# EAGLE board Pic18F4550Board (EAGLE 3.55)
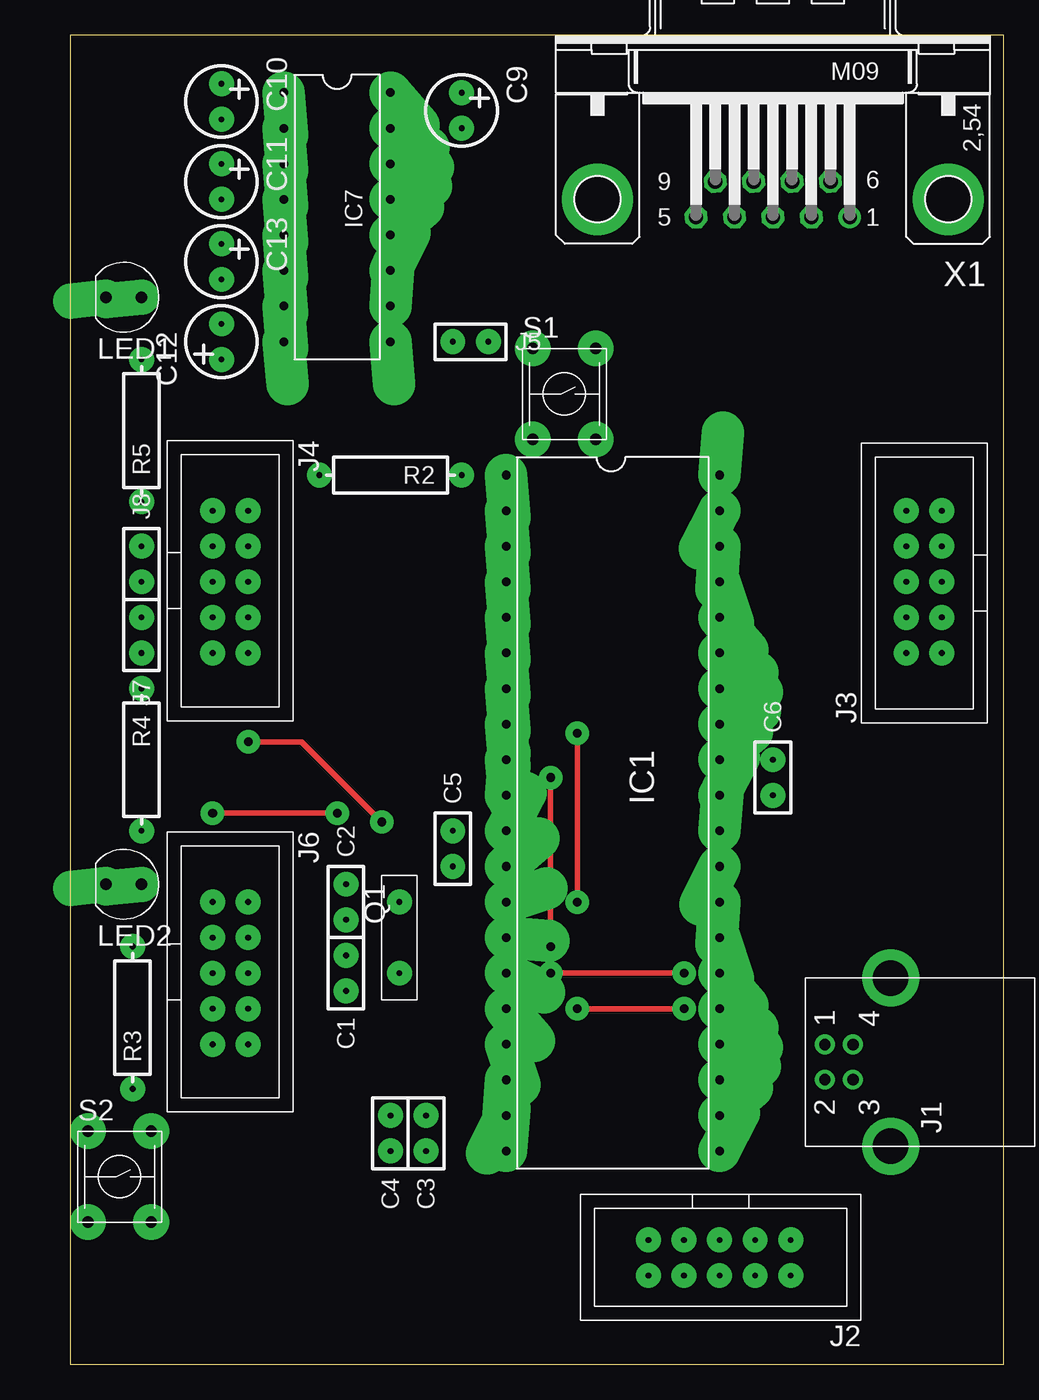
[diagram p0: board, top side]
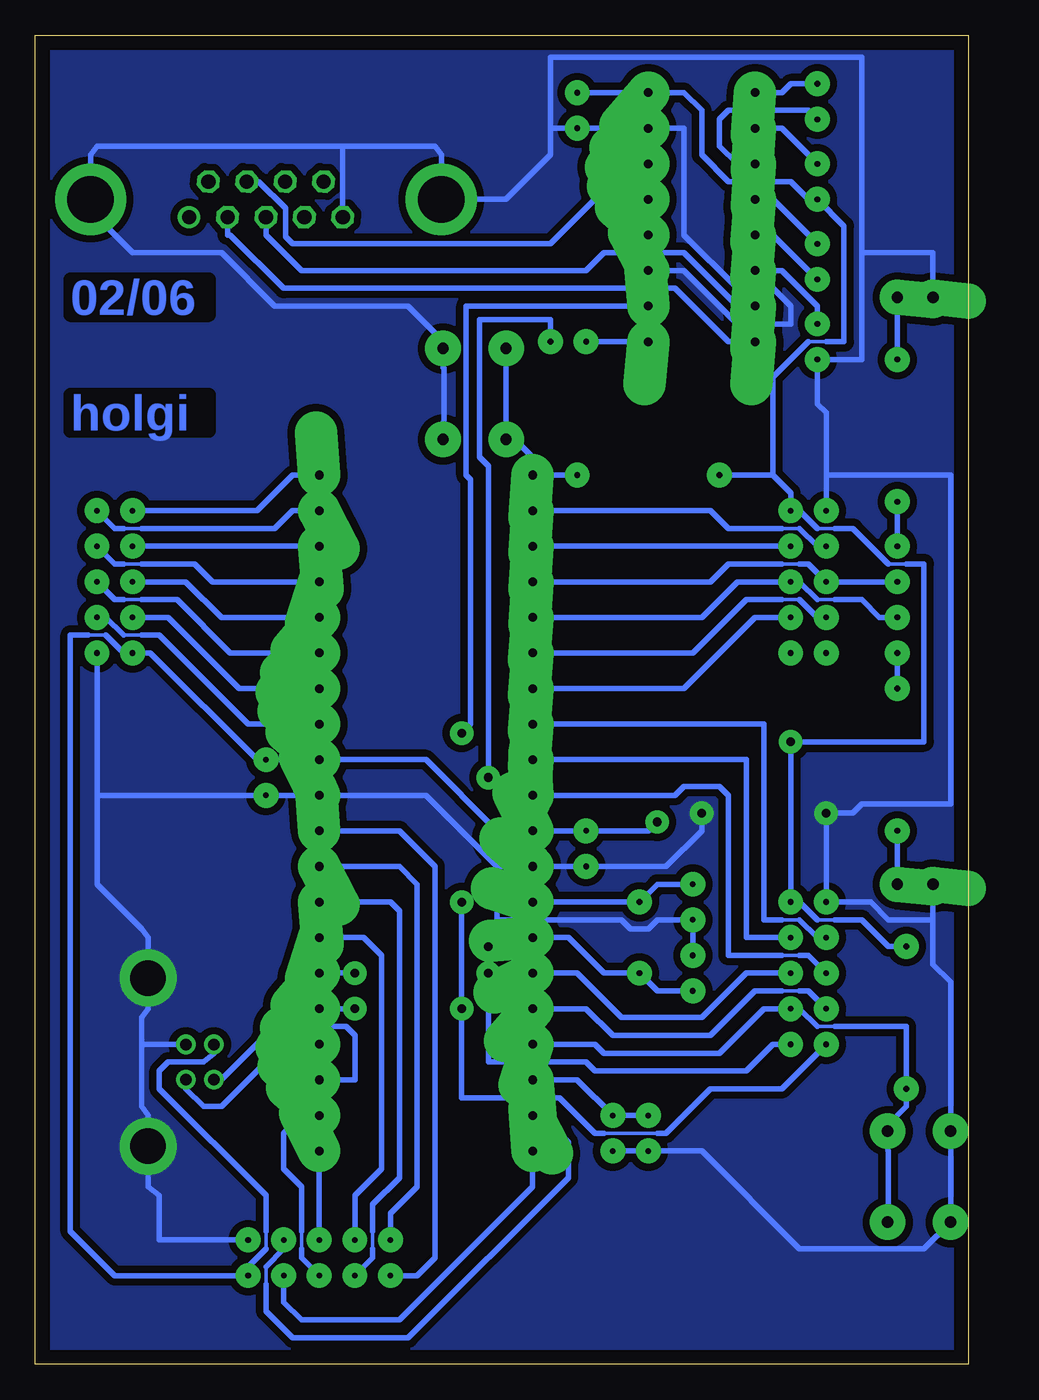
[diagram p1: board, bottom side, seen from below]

Size 66.66 x 94.92 mm. Coordinates in mm from the lower left corner, seen from the top.
Outline: 0,0 66.66,0 66.66,94.92 0,94.92 0,0
Copper layers used: Top, Bottom

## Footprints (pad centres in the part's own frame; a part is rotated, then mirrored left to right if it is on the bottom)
RM2,5 = drill 0.406 pad 1.778 round:  -1.27,0;  1.27,0
KO01 = drill 0.406 pad 1.778 round:  -1.27,0;  1.27,0
L-40B = drill 0.61 pad 3.048 offset:  -24.13,-7.62;  -21.59,-7.62;  -8.89,-7.62;  -6.35,-7.62;  -19.05,-7.62;  -16.51,-7.62;  -11.43,-7.62;  -13.97,-7.62;  -3.81,-7.62;  -1.27,-7.62;  1.27,-7.62;  3.81,-7.62;  6.35,-7.62;  8.89,-7.62;  11.43,-7.62;  13.97,-7.62;  16.51,-7.62;  19.05,-7.62;  21.59,-7.62;  24.13,-7.62;  24.13,7.62;  21.59,7.62;  19.05,7.62;  16.51,7.62;  13.97,7.62;  11.43,7.62;  8.89,7.62;  6.35,7.62;  3.81,7.62;  1.27,7.62;  -1.27,7.62;  -3.81,7.62;  -6.35,7.62;  -8.89,7.62;  -11.43,7.62;  -13.97,7.62;  -16.51,7.62;  -19.05,7.62;  -21.59,7.62;  -24.13,7.62
L-16B = drill 0.61 pad 3.048 offset:  -8.89,-3.81;  -6.35,-3.81;  6.35,-3.81;  8.89,-3.81;  -3.81,-3.81;  -1.27,-3.81;  3.81,-3.81;  1.27,-3.81;  8.89,3.81;  6.35,3.81;  3.81,3.81;  1.27,3.81;  -1.27,3.81;  -3.81,3.81;  -6.35,3.81;  -8.89,3.81
B_B = drill 2.54 pad 4.064 round: 1 6,-2.7; 2 -6,-2.7 | drill 0.813 pad 1.422 round:  1.25,0;  -1.25,0;  1.25,2;  -1.25,2
5 = drill 0.406 pad 1.778 round:  0,0;  2.54,0;  5.08,0;  7.62,0;  10.16,0;  10.16,2.54;  7.62,2.54;  5.08,2.54;  2.54,2.54;  0,2.54
MPER = drill 0.406 pad 1.778 round:  -1.27,0;  1.27,0
D_5MM = drill 0.813 pad 2.54 offset:  -1.27,0;  1.27,0
ARZ_ST = drill 0.406 pad 1.778 round:  -2.54,0;  2.54,0
S04 = drill 0.406 pad 1.778 round:  -5.08,0;  5.08,0
US = drill 0.813 pad 2.54 round:  0,0;  4.5,0;  4.5,6.5;  0,6.5
9HP = drill 1.016 pad 1.6 octagon:  5.486,1.27;  2.743,1.27;  0,1.27;  -2.743,1.27;  4.115,-1.27;  1.372,-1.27;  -1.372,-1.27;  -4.115,-1.27 | drill 1.016 pad 1.6 round:  -5.486,1.27 | drill 3.302 pad 5.08 round:  -12.522,0;  12.522,0

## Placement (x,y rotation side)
C1  15p  [RM2,5]  19.68,27.94 270 top
C2  15p  [RM2,5]  19.68,33.02 90 top
C3  100n  [RM2,5]  25.4,16.51 270 top
C4  100n  [RM2,5]  22.86,16.51 270 top
C5  100n  [RM2,5]  27.3,36.83 90 top
C6  100n  [RM2,5]  50.16,41.91 90 top
C9  10u  [KO01]  27.94,89.53 270 top
C10  1u  [KO01]  10.79,90.17 270 top
C11  1u  [KO01]  10.79,84.45 270 top
C12  1u  [KO01]  10.79,73.03 90 top
C13  1u  [KO01]  10.79,78.74 270 top
IC1  P18F4550  [L-40B]  38.73,39.37 270 top
IC7  MAX232  [L-16B]  19.05,81.92 270 top
J1  USB_B  [B_B]  55.88,21.59 90 top
J2  8BITPORT  [5]  51.44,8.89 180 top
J3  8BITPORT  [5]  62.23,50.8 90 top
J4  8BITPORT  [5]  10.16,60.96 270 top
J5  JUMPER  [MPER]  28.57,73.03 0 top
J6  8BITPORT  [5]  10.16,33.02 270 top
J7  JUMPER  [MPER]  5.08,52.07 270 top
J8  JUMPER  [MPER]  5.08,57.15 90 top
LED1  Green  [D_5MM]  3.81,76.2 180 top
LED2  Red  [D_5MM]  3.81,34.29 180 top
Q1  20.0MHz  [ARZ_ST]  23.5,30.48 270 top
R2  10k  [S04]  22.86,63.5 180 top
R3  10k  [S04]  4.45,24.77 90 top
R4  1k  [S04]  5.08,43.18 270 top
R5  1k  [S04]  5.08,66.67 90 top
S1  Reset  [US]  33.02,66.04 0 top
S2  Boot  [US]  1.27,10.16 0 top
X1  M09HP  [9HP]  50.16,83.19 180 top

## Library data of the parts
C1-C6 IC1 J2-J8 Q1 R2-R5 S1 S2 = holg_plt
C9-C13 LED1 LED2 = holgnorm
IC7 = maxim
J1 = 8031bord
X1 = subd-a

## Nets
+5V: C5. C6. C9. C11. IC1. IC7. J1. J2. J3. J4. J6. R2. R3.
GND: C1. C2. C3. C4. C5. C6. C9. C12. IC1. IC7. J1. J1.1 J1.2 J2. J3. J4. J6. LED1. LED2. S1. S2. X1.
N$1: C3. C4. IC1.
N$2: C12. IC7.
N$3: IC1. J2.
N$4: C2. IC1. Q1.
N$5: C1. IC1. Q1.
N$6: IC1. J2.
N$7: IC1. J2.
N$8: IC1. J1.
N$9: IC1. J1.
N$10: IC1. J2.
N$11: IC1. J2.
N$12: IC1. J2.
N$13: IC1. J2.
N$14: IC1. J2.
N$15: IC1. J3.
N$16: IC1. R2. S1.
N$17: IC1. J3.
N$18: IC1. J3.
N$19: IC1. J3.
N$20: IC1. J3.
N$21: IC1. J3.
N$22: IC1. J3.
N$23: IC1. J3.
N$24: C11. IC7.
N$25: C10. IC7.
N$26: C13. IC7.
N$27: C10. IC7.
N$28: C13. IC7.
N$29: IC1. J4.
N$30: IC1. J4.
N$31: IC1. J4. J8.
N$32: IC1. J4. J7.
N$33: IC1. J4.
N$34: IC1. J4.
N$35: IC7. J5.
N$40: LED2. R4.
N$41: LED1. R5.
N$42: J8. R5.
N$43: J7. R4.
RC0: IC1. J6.
RC1: IC1. J6.
RC2: IC1. J6. R3. S2.
RE0: IC1. J6.
RE1: IC1. J6.
RE2: IC1. J6.
RTS_OUT: IC7. X1.
RXD: IC1. J5. J6.
RXD_IN: IC7. X1.
TXD: IC1. IC7. J6.
TXD_OUT: IC7. X1.

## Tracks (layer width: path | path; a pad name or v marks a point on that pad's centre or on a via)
+5V  (via drill 0.61 pad 1.68)
  Top 0.406: v12.7,44.45 16.51,44.45 v22.23,38.73
  Bottom 0.254: 9.53,59.69 10.79,59.69 | 50.16,8.26 50.16,9.53 | 11.43,73.03 10.16,73.03 | 9.53,31.75 10.79,31.75 | 4.45,57.15 5.71,57.15 | 62.87,52.07 61.59,52.07
  Bottom 0.406: 13.97,63.5 12.7,62.23 J4. 12.06,60.96 10.79,59.69 | 13.97,63.5 R2. | 9.53,59.69 8.26,59.69 5.71,57.15 | v22.23,38.73 22.86,38.1 C5. 31.11,38.1 33.66,38.1 38.73,43.18 46.35,43.18 C6. 50.8,43.18 58.42,50.8 J3. 60.33,50.8 61.59,52.07 | 50.16,8.26 51.44,6.99 J2. 60.96,6.35 64.14,9.53 64.14,52.07 62.87,52.07 | 50.16,9.53 50.16,12.06 57.78,19.68 57.78,20.95 57.15,21.59 54.61,21.59 53.88,22.23 53.88,22.84 | 27.94,90.81 IC7. 20.32,90.81 19.05,89.53 19.05,86.36 17.14,84.45 12.7,84.45 11.43,83.19 C11. 8.89,81.28 8.89,73.03 10.16,73.03 | 13.97,63.5 13.97,70.48 11.43,73.03 | 10.79,31.75 12.06,33.02 J6. v12.7,44.45 3.17,44.45 3.17,57.15 4.45,57.15 | 9.53,31.75 7.62,31.75 5.71,29.84 R3.
GND  (via drill 0.61 pad 1.68)
  Top 0.406: v10.16,39.37 v19.05,39.37
  Bottom 0.406: C3. C4. 19.05,15.24 12.06,8.26 3.17,8.26 1.27,10.16 S2. 1.27,27.3 2.54,28.57 2.54,31.75 | 19.68,29.21 19.68,31.75 22.23,31.75 22.86,31.11 24.13,31.11 24.77,31.75 33.66,31.75 33.66,35.56 | 33.66,35.56 31.11,35.56 27.3,35.56 21.59,35.56 19.05,38.1 v19.05,39.37 | 33.66,35.56 38.73,40.64 46.35,40.64 50.16,40.64 62.23,40.64 | 62.23,40.64 62.23,50.8 | 51.44,8.89 57.78,8.89 57.78,12.06 58.58,12.7 J1.2 58.58,17.78 59.05,18.41 59.05,22.86 | 55.88,22.84 57.78,22.84 57.78,22.86 59.05,22.86 | 59.05,22.86 59.05,24.77 58.58,25.4 J1.1 58.58,30.48 59.05,31.11 62.23,34.29 62.23,40.64 | 10.16,63.5 10.16,67.94 10.79,68.58 10.79,71.75 7.62,71.75 7.62,79.38 | 7.62,79.38 7.62,93.34 29.84,93.34 29.84,88.27 | 29.84,88.27 C9. 22.86,88.27 20.32,88.27 20.32,80.64 16.51,76.83 13.97,76.83 12.7,75.56 12.7,74.3 16.51,74.3 20.32,78.11 22.86,78.11 | 29.84,88.27 29.84,86.36 33.02,83.19 X1. 37.64,86.36 38.1,87 44.45,87 | 44.68,81.92 44.68,87 44.45,87 | 44.45,87 62.23,87 62.69,86.36 62.69,83.19 62.69,82.37 59.69,79.38 53.34,79.38 49.53,75.56 40.01,75.56 37.52,73.08 37.52,72.54 37.52,71.17 37.47,71.12 37.47,67.31 37.52,67.25 37.52,66.04 | 2.54,31.75 LED2. | 2.54,31.75 5.71,31.75 6.99,33.02 10.16,33.02 v10.16,39.37 8.26,39.37 7.62,40.01 1.27,40.01 1.27,63.5 10.16,63.5 | LED1. 2.54,79.38 7.62,79.38 | 10.16,63.5 10.16,60.96
  pour Bottom (isolate 0.508): 0.64,0.64 0.64,93.98 66.04,93.98 66.04,0.64
N$1
  Bottom 0.406: 22.86,17.78 25.4,17.78 27.94,20.32 31.11,20.32
N$2
  Bottom 0.406: C12. 10.79,75.56 13.34,78.11 15.24,78.11
N$3
  Bottom 0.406: 46.35,38.1 40.64,38.1 38.1,35.56 38.1,7.62 39.37,6.35 41.27,6.35
N$4
  Bottom 0.406: 31.11,33.02 23.5,33.02 22.23,34.29 C2.
N$5
  Bottom 0.406: 31.11,30.48 28.57,30.48 26.04,27.94 Q1. 22.23,26.67 C1.
N$6
  Bottom 0.406: 46.35,35.56 40.64,35.56 39.37,34.29 39.37,12.7 41.27,10.79 41.27,8.89
N$7
  Bottom 0.254: 42.55,8.26 42.55,9.53
  Bottom 0.406: 46.35,33.02 41.27,33.02 40.64,32.38 40.64,13.34 42.55,11.43 42.55,9.53 | 43.81,6.35 42.55,7.62 42.55,8.26
N$8
  Bottom 0.406: 46.35,20.32 43.81,20.32 43.81,23.5 44.45,24.13 49.53,24.13 52.07,21.59 53.34,20.34 J1.
N$9
  Bottom 0.406: 55.88,20.34 55.88,19.68 54.61,18.41 53.34,18.41 48.9,22.86 46.35,22.86
N$10
  Bottom 0.406: 46.35,30.48 43.18,30.48 41.91,29.21 41.91,13.97 43.81,12.06 43.81,8.89
N$11
  Bottom 0.254: 47.62,8.26 47.62,9.53
  Bottom 0.406: 46.35,17.78 47.62,17.78 48.9,16.51 48.9,13.97 47.62,12.7 47.62,9.53 | 46.35,6.35 47.62,7.62 47.62,8.26
N$12
  Bottom 0.406: 46.35,8.89 46.35,15.24
N$13
  Bottom 0.406: 31.11,15.24 31.11,12.7 40.64,3.17 47.62,3.17 48.9,4.45 48.9,6.35
N$14
  Bottom 0.254: 50.16,5.71 50.16,6.99
  Bottom 0.406: 31.11,17.78 30.48,17.78 28.57,15.88 28.57,13.34 40.01,1.91 48.26,1.91 50.16,3.81 50.16,5.71 | 48.9,8.89 48.9,8.26 50.16,6.99
N$15
  Bottom 0.406: IC1. 48.26,63.5 50.8,60.96 59.69,60.96
N$16
  Bottom 0.406: 27.94,63.5 31.11,63.5 31.11,64.77 32.38,66.04 33.02,66.04 S1.
N$17
  Bottom 0.254: 59.05,59.69 60.33,59.69
  Bottom 0.406: 46.35,60.96 48.26,60.96 49.53,59.69 59.05,59.69 | 62.23,60.96 60.96,59.69 60.33,59.69
N$18
  Bottom 0.406: 46.35,58.42 59.69,58.42
N$19
  Bottom 0.254: 59.05,57.15 60.33,57.15
  Bottom 0.406: 46.35,55.88 53.98,55.88 55.24,57.15 59.05,57.15 | 62.23,58.42 60.96,57.15 60.33,57.15
N$20
  Bottom 0.406: 46.35,53.34 53.34,53.34 55.88,55.88 59.69,55.88
N$21
  Bottom 0.254: 59.05,54.61 60.33,54.61
  Bottom 0.406: 46.35,50.8 52.7,50.8 56.52,54.61 59.05,54.61 | 62.23,55.88 60.96,54.61 60.33,54.61
N$22
  Bottom 0.406: 46.35,48.26 52.07,48.26 57.15,53.34 59.69,53.34
N$23
  Bottom 0.254: 59.05,52.07 60.33,52.07
  Bottom 0.406: 46.35,45.72 51.44,45.72 57.78,52.07 59.05,52.07 | 62.23,53.34 61.59,53.34 60.33,52.07
N$24
  Bottom 0.406: 15.24,88.27 13.34,88.27 10.79,85.72
N$25
  Bottom 0.406: 15.24,85.72 16.51,85.72 17.78,87 17.78,88.9 17.14,89.53 11.43,89.53 C10.
N$26
  Bottom 0.406: 15.24,80.64 13.97,80.64 C13.
N$27
  Bottom 0.406: 15.24,90.81 13.34,90.81 12.7,91.44 10.79,91.44
N$28
  Bottom 0.406: 15.24,83.19 13.97,83.19 10.79,80.01
N$29
  Bottom 0.254: 12.06,59.69 13.34,59.69
  Bottom 0.406: 31.11,60.96 18.41,60.96 17.14,59.69 13.34,59.69 | 10.16,58.42 10.79,58.42 12.06,59.69
N$30
  Bottom 0.406: 12.7,58.42 31.11,58.42
N$31
  Bottom 0.254: 12.06,57.15 13.34,57.15
  Bottom 0.406: 12.06,57.15 11.43,57.15 10.16,55.88 5.08,55.88 | 31.11,55.88 18.41,55.88 17.14,57.15 13.34,57.15
N$32
  Bottom 0.254: 9.53,54.61 10.79,54.61
  Bottom 0.406: 31.11,53.34 19.05,53.34 16.51,55.88 12.7,55.88 12.06,55.88 10.79,54.61 | 5.08,53.34 6.35,53.34 7.62,54.61 9.53,54.61
N$33
  Bottom 0.254: 12.06,54.61 13.34,54.61
  Bottom 0.406: 31.11,50.8 19.68,50.8 15.88,54.61 13.34,54.61 | 10.16,53.34 10.79,53.34 12.06,54.61
N$34
  Bottom 0.406: 31.11,48.26 20.32,48.26 15.24,53.34 12.7,53.34
N$35
  Bottom 0.406: 22.86,73.03 27.3,73.03
N$40
  Bottom 0.406: 5.08,34.29 R4.
N$41
  Bottom 0.406: R5. 5.08,76.2
N$42
  Bottom 0.406: J8. 5.08,61.59
N$43
  Bottom 0.406: 5.08,48.26 J7.
RC0
  Bottom 0.406: 12.7,27.94 15.88,27.94 19.05,24.77 24.77,24.77 27.94,27.94 31.11,27.94
RC1
  Bottom 0.254: 12.06,26.67 13.34,26.67
  Bottom 0.406: 31.11,25.4 27.3,25.4 25.4,23.5 18.41,23.5 15.24,26.67 13.34,26.67 | 10.16,25.4 11.43,26.67 12.06,26.67
RC2
  Bottom 0.254: 9.53,24.13 10.79,24.13
  Bottom 0.406: 31.11,22.86 26.67,22.86 26.04,22.23 17.78,22.23 14.61,25.4 12.7,25.4 12.06,25.4 10.79,24.13 | 5.77,10.16 5.77,11.38 5.71,11.43 5.71,15.24 5.77,15.29 5.77,16.66 5.77,17.09 4.45,18.41 4.45,19.68 4.45,24.13 9.53,24.13
RE0
  Bottom 0.254: 12.06,31.75 13.34,31.75
  Bottom 0.406: 31.11,45.72 14.61,45.72 14.61,31.75 13.34,31.75 | 10.16,30.48 10.79,30.48 12.06,31.75
RE1
  Bottom 0.406: 31.11,43.18 15.88,43.18 15.88,30.48 12.7,30.48
RE2
  Bottom 0.254: 12.06,29.21 13.34,29.21
  Bottom 0.406: 31.11,40.64 20.95,40.64 20.32,41.27 17.78,41.27 17.14,40.64 17.14,29.21 13.34,29.21 | 10.16,27.94 11.43,29.21 12.06,29.21
RTS_OUT
  Bottom 0.406: 22.86,85.72 24.13,85.72 29.84,80.01 48.26,80.01 48.77,80.52 48.77,82.55 50.67,84.45 51.54,84.45 51.56,84.45
RXD  (via drill 0.61 pad 1.68)
  Top 0.406: v34.29,27.94 v43.81,27.94 | v34.29,29.84 v34.29,41.91
  Bottom 0.406: 12.7,22.86 13.97,22.86 15.88,20.95 26.67,20.95 27.3,21.59 34.29,21.59 v34.29,27.94 v34.29,29.84 | v43.81,27.94 46.35,27.94 | J5. 29.84,74.61 34.92,74.61 34.92,64.77 34.29,64.14 v34.29,41.91
RXD_IN
  Bottom 0.406: 15.24,73.03 17.14,73.03 20.95,76.83 48.9,76.83 52.7,80.64 52.91,80.64 52.91,81.92
TXD  (via drill 0.61 pad 1.68)
  Top 0.406: v36.2,25.4 v43.81,25.4 | v36.2,33.02 v36.2,45.09
  Bottom 0.254: 22.23,16.51 26.04,16.51
  Bottom 0.406: v43.81,25.4 46.35,25.4 | 26.04,16.51 26.67,16.51 29.21,19.05 36.2,19.05 v36.2,25.4 v36.2,33.02 | v36.2,45.09 35.56,45.72 35.56,63.18 35.88,63.5 35.88,75.56 22.86,75.56 | 22.23,16.51 21.59,16.51 18.41,19.68 13.34,19.68 10.16,22.86
TXD_OUT
  Bottom 0.406: 15.24,75.56 16.51,75.56 20.32,79.38 26.04,79.38 27.3,78.11 47.62,78.11 50.16,80.64 50.16,81.92

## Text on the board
Bottom: 02/06 | holgi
